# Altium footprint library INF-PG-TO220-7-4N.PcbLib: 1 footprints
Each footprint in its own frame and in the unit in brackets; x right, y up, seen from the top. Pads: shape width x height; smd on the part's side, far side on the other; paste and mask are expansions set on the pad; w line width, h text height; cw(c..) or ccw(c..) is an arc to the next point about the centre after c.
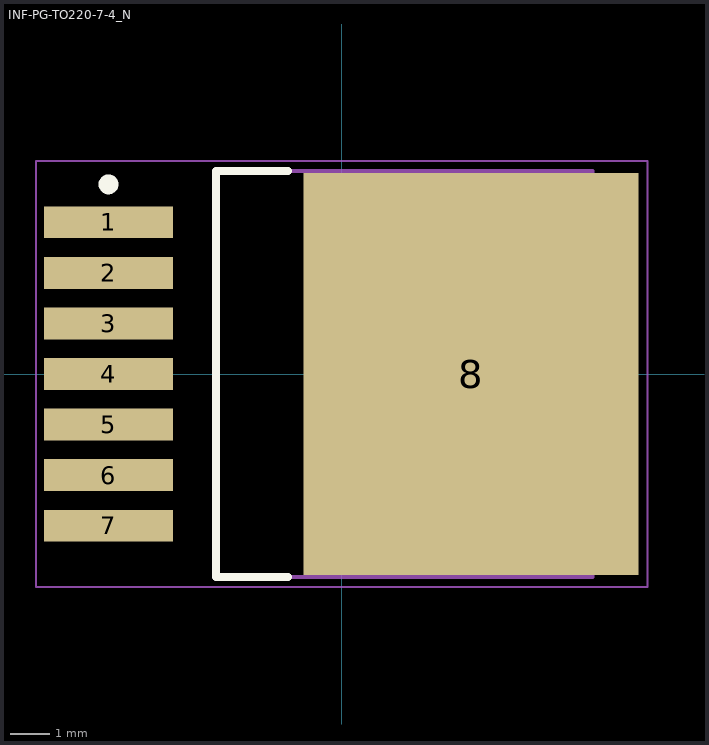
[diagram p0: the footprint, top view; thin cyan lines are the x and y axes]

## INF-PG-TO220-7-4_N [mm] "DPAK, 7-Leads, Body 10x9.25mm, Pitch 1.27mm, IPC Medium Density"
height 4.4
pads (8):
  rect 3.25x0.8 smd: 1(-5.85,3.81) 2(-5.85,2.54) 3(-5.85,1.27) 4(-5.85,0) 5(-5.85,-1.27) 6(-5.85,-2.54) 7(-5.85,-3.81)
  rect 8.4x10.1 smd: 8(3.25,0)
Top Overlay:
  circle w0.25: c-5.85,4.76 r0.125
  lines w0.2: -1.35,-5.1 -3.15,-5.1 -3.15,5.1 -1.35,5.1
Mechanical 13:
  lines w0.1: -3.15,-5.1 6.3,-5.1 6.3,5.1 -3.15,5.1 -3.15,-5.1
Mechanical 15:
  lines w0.05: -7.675,-5.35 7.675,-5.35 7.675,5.35 -7.675,5.35 -7.675,-5.35
  lines w0.1: -0.5,0 0.5,0 ; 0,-0.5 0,0.5
3D body: height 4.4, standoff 0.1, extent -3.15,-5.1 6.3,5.1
